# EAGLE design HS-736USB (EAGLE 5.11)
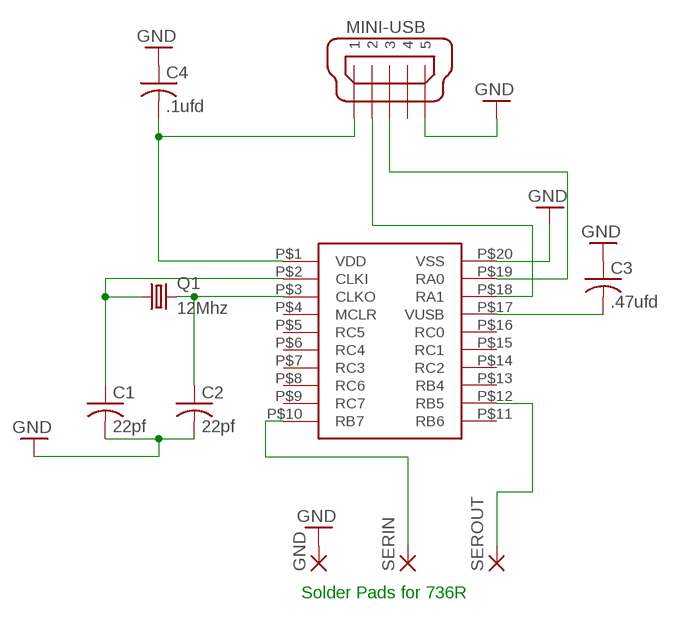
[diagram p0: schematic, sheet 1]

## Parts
C1  22pf  C-USC1206  [C1206]
C2  22pf  C-USC1206  [C1206]
C3  .47ufd  C-USC1206  [C1206]
C4  .1ufd  C-USC1206  [C1206]
GND  3,17/1,3  [3,17/1,3]
MINI-USB  MINI-USB-UX60-MB-5ST  [UX60-MB-5ST]
Q1  12Mhz  CRYSTALHC49S  [HC49/S]
SERIN  3,17/1,3  [3,17/1,3]
SEROUT  3,17/1,3  [3,17/1,3]
U$1  14K50_DIP  [14K50_DIP]

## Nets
GND: C1.2 C2.2 C3.1 C4.1 GND.1(P) MINI-USB.5 U$1.P$20(VSS)
N$1: C2.1 Q1.2 U$1.P$3(CLKO)
N$2: C1.1 Q1.1 U$1.P$2(CLKI)
N$4: C4.2 MINI-USB.1 U$1.P$1(VDD)
N$6: C3.2 U$1.P$17(VUSB)
N$7: MINI-USB.2 U$1.P$18(RA1)
N$8: MINI-USB.3 U$1.P$19(RA0)
N$9: SEROUT.1(P) U$1.P$12(RB5)
N$10: SERIN.1(P) U$1.P$10(RB7)
Unconnected: MINI-USB.4 U$1.P$4(MCLR) U$1.P$5(RC5) U$1.P$6(RC4) U$1.P$7(RC3) U$1.P$8(RC6) U$1.P$9(RC7) U$1.P$11(RB6) U$1.P$13(RB4) U$1.P$14(RC2) U$1.P$15(RC1) U$1.P$16(RC0)

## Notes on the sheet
- Solder Pads for 736R

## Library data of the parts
C1-C4 = rcl:C-US: CAPACITOR, American symbol
GND SERIN SEROUT = wirepad:3,17/1,3: THROUGH-HOLE PAD
MINI-USB = con-hirose:MINI-USB-: MINI USB Connector Source: http://www.hirose.co.jp/cataloge_hp/e24000019.pdf; OC_FARNELL: unknown; OC_NEWARK: unknown
Q1 = crystal:CRYSTAL: CRYSTAL; OC_FARNELL: 1667008; OC_NEWARK: unknown
U$1 = 14K50_dip:14K50_DIP: 14K50 20pin dip

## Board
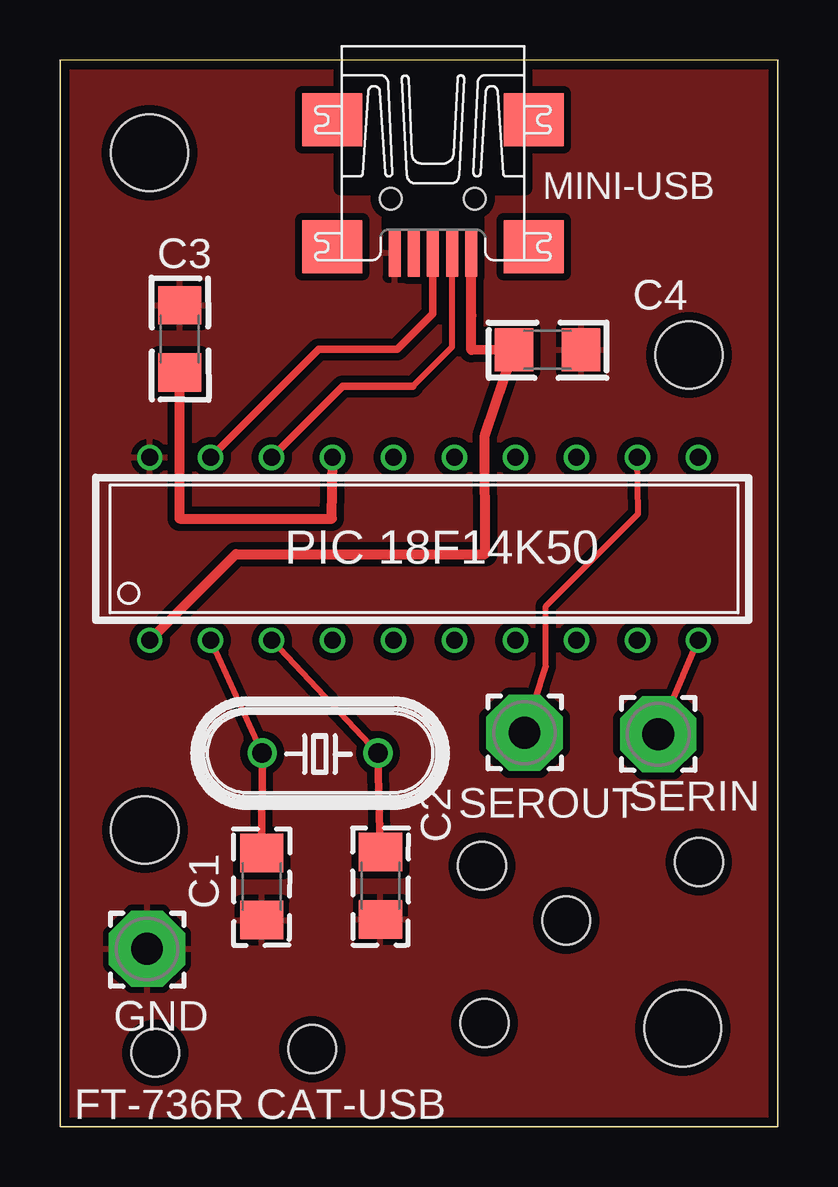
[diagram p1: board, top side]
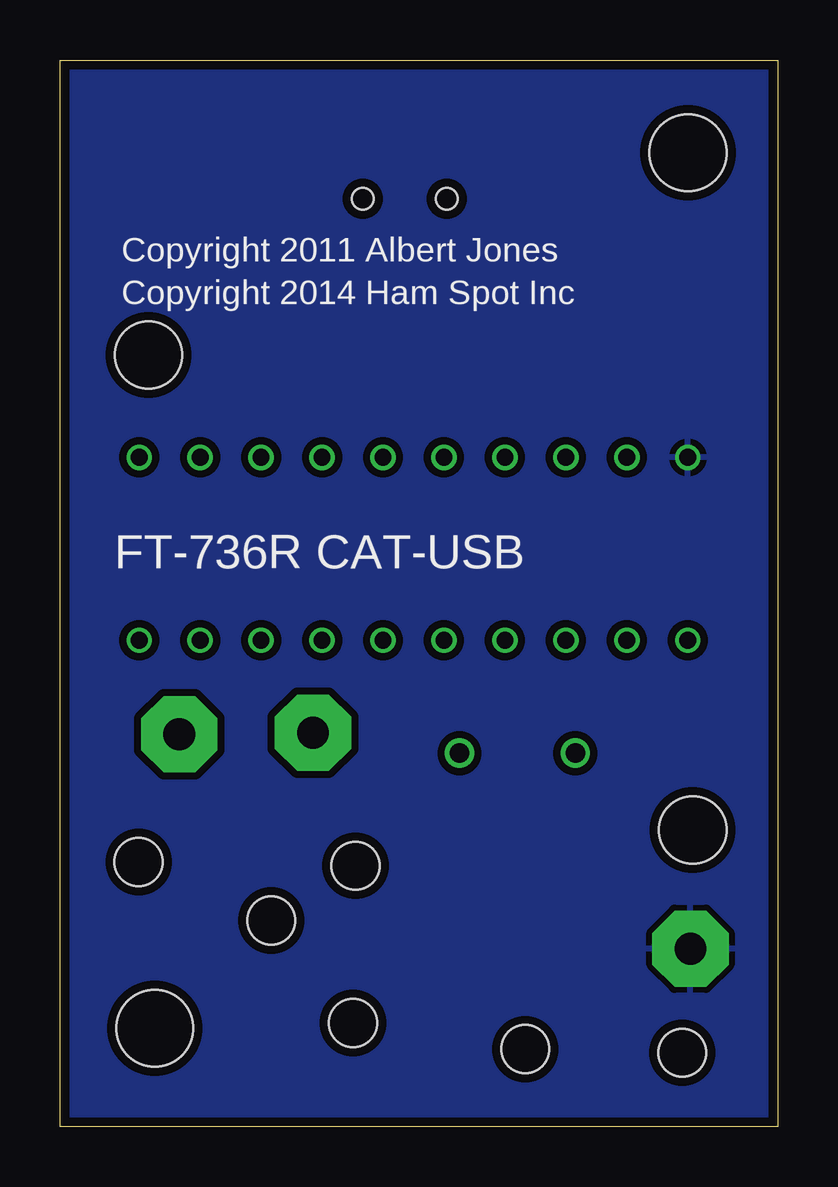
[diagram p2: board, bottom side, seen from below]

Size 29.9 x 44.44 mm. Coordinates in mm from the lower left corner, seen from the top.
Outline: 0,0 29.9,0 29.9,44.44 0,44.44 0,0
Copper layers (1*16): Top 0.0356mm / dielectric 1.5011mm / Bottom 0.0356mm
Design rules "LaenPCBOrder": minimum track width 6mil, minimum drill 13mil, track to track 6mil, track to pad 6mil, pad to pad 6mil, via to via 6mil, smd to smd 6mil, copper to edge 15mil, drill to drill 6mil, minimum pad ring 7mil, minimum via ring 7mil, stop-mask expansion 3mil, vias tented up to drill 0mil, thermal gap 10mil
Holes 2.8 mm at 3.53,12.36 26.21,32.15
Holes 2 mm at 17.58,10.87 17.69,4.32 26.62,11.02 3.97,3.07 10.51,3.22 21.09,8.58
Holes 3.2 mm at 25.95,4.09 3.73,40.57

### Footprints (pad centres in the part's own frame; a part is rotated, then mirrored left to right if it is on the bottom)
C1206 = smd 1.6 x 1.8: 1 -1.4,0; 2 1.4,0
3,17/1,3 = drill 1.321 pad 3.175 octagon: 1 0,0
UX60-MB-5ST = smd 2 x 0.5: 1 2.25,1.6; 2 2.25,0.8; 3 2.25,0; 4 2.25,-0.8; 5 2.25,-1.6 | smd 2.2 x 2.5: M1 -3.3,-4.2; M2 -3.3,4.2; M3 2,4.2; M4 2,-4.2 | hole 0.9: 0,-1.75; 0,1.75
HC49/S = drill 0.813: 1 -2.413,0; 2 2.413,0
14K50_DIP = drill 0.7: P$1 -1.524,24.511; P$2 -1.524,21.971; P$3 -1.524,19.431; P$4 -1.524,16.891; P$5 -1.524,14.351; P$6 -1.524,11.811; P$7 -1.524,9.271; P$8 -1.524,6.731; P$9 -1.524,4.191; P$10 -1.524,1.651; P$11 6.096,1.651; P$12 6.096,4.191; P$13 6.096,6.731; P$14 6.096,9.271; P$15 6.096,11.811; P$16 6.096,14.351; P$17 6.096,16.891; P$18 6.096,19.431; P$19 6.096,21.971; P$20 6.096,24.511

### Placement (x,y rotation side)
C1  8.41,10 270 top
C2  13.35,10.04 270 top
C3  4.99,32.82 270 top
C4  20.31,32.37 180 top
GND  3.63,7.4 0 top
MINI-USB  15.54,38.65 270 top
Q1  10.84,15.56 0 top
SERIN  24.93,16.35 0 top
SEROUT  19.36,16.41 0 top
U$1  28.25,21.79 90 top

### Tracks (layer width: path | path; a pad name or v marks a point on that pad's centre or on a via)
GND
  pour Top (isolate 0.305): 0,44.45 29.9,44.45 29.9,0 0,0
  pour Bottom (isolate 0.305): 0,44.45 29.9,44.45 29.9,0 0,0
N$1
  Top 0.254: Q1.2 U$1.P$3
  Top 0.305: C2.1 Q1.2
N$2
  Top 0.254: Q1.1 U$1.P$2
  Top 0.305: C1.1 Q1.1
N$4
  Top 0.406: MINI-USB.1 17.14,33.8 17.14,32.35 C4.2 17.71,28.81 17.71,23.85 7.33,23.85 U$1.P$1
N$6
  Top 0.406: C3.2 4.99,25.33 11.33,25.33 U$1.P$17
N$7
  Top 0.254: 14.7,30.84 16.34,32.49 MINI-USB.2
  Top 0.305: 14.7,30.84 11.78,30.84 U$1.P$18
N$8
  Top 0.305: U$1.P$19 10.78,32.38 14.05,32.38 15.54,33.88 MINI-USB.3
N$9
  Top 0.254: SEROUT.1 20.25,19.16 20.25,21.68 24.09,25.52 U$1.P$12
N$10
  Top 0.254: SERIN.1 U$1.P$10

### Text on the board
_tsilk: MINI-USB | FT-736R CAT-USB
_bsilk: Copyright 2011 Albert Jones | Copyright 2014 Ham Spot Inc | FT-736R CAT-USB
